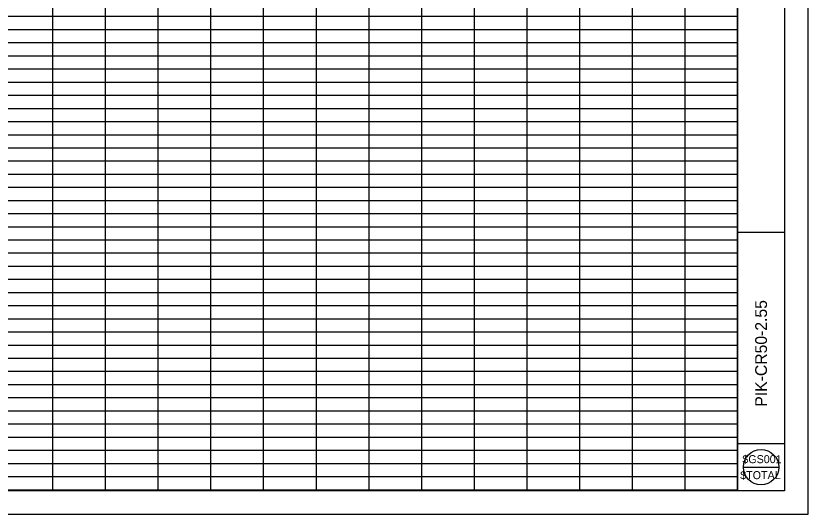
# Model space of a CAD drawing. Extents: x 0 to 34, y 0 to 22.
# Drawn here: x 17.17 to 34, y 0 to 10.6 of the extents above; entities that cross this region are included whole.
import ezdxf

# ---------------------------------------------------------------- set-up
doc = ezdxf.new("R2010")
doc.units = 0
for name, color, linetype in [('SH_Border', 7, 'Continuous'), ('SH_Cut_Line', 7, 'Continuous'), ('SH_Data', 7, 'Continuous')]:
    doc.layers.add(name, color=color, linetype=linetype)

msp = doc.modelspace()

# ---------------------------------------------------------------- linework, layer by layer
at = {"layer": 'SH_Border'}
for p, q in [((32.5, 0.5), (32.5, 21.5)), ((32.5, 6), (33.5, 6)), ((32.5, 1.5), (33.5, 1.5))]:
    msp.add_line(p, q, dxfattribs=at)
msp.add_lwpolyline([(2, 21.5), (33.5, 21.5), (33.5, 0.5), (2, 0.5)], close=True, dxfattribs=at)
at = {"layer": 'SH_Cut_Line'}
msp.add_lwpolyline([(0, 0), (34, 0), (34, 22), (0, 22)], close=True, dxfattribs=at)
at = {"layer": 'SH_Data'}
for p, q in [((17.945, 11.99), (17.945, 10.591)), ((19.065, 11.99), (19.065, 10.591)), ((20.184, 11.99), (20.184, 10.591)), ((21.304, 11.99), (21.304, 10.591)), ((22.423, 11.99), (22.423, 10.591)), ((23.543, 11.99), (23.543, 10.591)), ((24.663, 11.99), (24.663, 10.591)), ((25.782, 11.99), (25.782, 10.591)), ((26.902, 11.99), (26.902, 10.591)), ((28.022, 11.99), (28.022, 10.591)), ((29.141, 11.99), (29.141, 10.591)), ((30.261, 11.99), (30.261, 10.591)), ((31.38, 11.99), (31.38, 10.591)), ((32.5, 11.99), (32.5, 10.591)), ((15.706, 10.591), (17.945, 10.591)), ((17.945, 10.591), (21.304, 10.591)), ((17.945, 10.591), (17.945, 9.192)), ((19.065, 10.591), (19.065, 9.192)), ((20.184, 10.591), (20.184, 9.192)), ((21.304, 10.591), (22.423, 10.591)), ((21.304, 10.591), (21.304, 9.192)), ((22.423, 10.591), (28.022, 10.591)), ((22.423, 10.591), (22.423, 9.192)), ((23.543, 10.591), (23.543, 9.192)), ((24.663, 10.591), (24.663, 9.192)), ((25.782, 10.591), (25.782, 9.192)), ((26.902, 10.591), (26.902, 9.192)), ((28.022, 10.591), (32.5, 10.591)), ((28.022, 10.591), (28.022, 9.192)), ((29.141, 10.591), (29.141, 9.192)), ((30.261, 10.591), (30.261, 9.192)), ((31.38, 10.591), (31.38, 9.192)), ((32.5, 10.591), (32.5, 9.192)), ((15.706, 10.311), (17.945, 10.311)), ((17.945, 10.311), (21.304, 10.311)), ((21.304, 10.311), (22.423, 10.311)), ((22.423, 10.311), (28.022, 10.311)), ((28.022, 10.311), (32.5, 10.311)), ((15.706, 10.032), (17.945, 10.032)), ((17.945, 10.032), (21.304, 10.032)), ((21.304, 10.032), (22.423, 10.032)), ((22.423, 10.032), (28.022, 10.032)), ((28.022, 10.032), (32.5, 10.032)), ((15.706, 9.752), (17.945, 9.752)), ((17.945, 9.752), (21.304, 9.752)), ((21.304, 9.752), (22.423, 9.752)), ((22.423, 9.752), (28.022, 9.752)), ((28.022, 9.752), (32.5, 9.752)), ((15.706, 9.472), (17.945, 9.472)), ((17.945, 9.472), (21.304, 9.472)), ((21.304, 9.472), (22.423, 9.472)), ((22.423, 9.472), (28.022, 9.472)), ((28.022, 9.472), (32.5, 9.472)), ((15.706, 9.192), (17.945, 9.192)), ((17.945, 9.192), (21.304, 9.192)), ((17.945, 9.192), (17.945, 7.794)), ((19.065, 9.192), (19.065, 7.794)), ((20.184, 9.192), (20.184, 7.794)), ((21.304, 9.192), (22.423, 9.192)), ((21.304, 9.192), (21.304, 7.794)), ((22.423, 9.192), (28.022, 9.192)), ((22.423, 9.192), (22.423, 7.794)), ((23.543, 9.192), (23.543, 7.794)), ((24.663, 9.192), (24.663, 7.794)), ((25.782, 9.192), (25.782, 7.794)), ((26.902, 9.192), (26.902, 7.794)), ((28.022, 9.192), (32.5, 9.192)), ((28.022, 9.192), (28.022, 7.794)), ((29.141, 9.192), (29.141, 7.794)), ((30.261, 9.192), (30.261, 7.794)), ((31.38, 9.192), (31.38, 7.794)), ((32.5, 9.192), (32.5, 7.794)), ((15.706, 8.913), (17.945, 8.913)), ((17.945, 8.913), (21.304, 8.913)), ((21.304, 8.913), (22.423, 8.913)), ((22.423, 8.913), (28.022, 8.913)), ((28.022, 8.913), (32.5, 8.913)), ((15.706, 8.633), (17.945, 8.633)), ((17.945, 8.633), (21.304, 8.633)), ((21.304, 8.633), (22.423, 8.633)), ((22.423, 8.633), (28.022, 8.633)), ((28.022, 8.633), (32.5, 8.633)), ((15.706, 8.353), (17.945, 8.353)), ((17.945, 8.353), (21.304, 8.353)), ((21.304, 8.353), (22.423, 8.353)), ((22.423, 8.353), (28.022, 8.353)), ((28.022, 8.353), (32.5, 8.353)), ((15.706, 8.073), (17.945, 8.073)), ((17.945, 8.073), (21.304, 8.073)), ((21.304, 8.073), (22.423, 8.073)), ((22.423, 8.073), (28.022, 8.073)), ((28.022, 8.073), (32.5, 8.073)), ((15.706, 7.794), (17.945, 7.794)), ((17.945, 7.794), (21.304, 7.794)), ((17.945, 7.794), (17.945, 6.395)), ((19.065, 7.794), (19.065, 6.395)), ((20.184, 7.794), (20.184, 6.395)), ((21.304, 7.794), (22.423, 7.794)), ((21.304, 7.794), (21.304, 6.395)), ((22.423, 7.794), (28.022, 7.794)), ((22.423, 7.794), (22.423, 6.395)), ((23.543, 7.794), (23.543, 6.395)), ((24.663, 7.794), (24.663, 6.395)), ((25.782, 7.794), (25.782, 6.395)), ((26.902, 7.794), (26.902, 6.395)), ((28.022, 7.794), (32.5, 7.794)), ((28.022, 7.794), (28.022, 6.395)), ((29.141, 7.794), (29.141, 6.395)), ((30.261, 7.794), (30.261, 6.395)), ((31.38, 7.794), (31.38, 6.395)), ((32.5, 7.794), (32.5, 6.395)), ((15.706, 7.514), (17.945, 7.514)), ((17.945, 7.514), (21.304, 7.514)), ((21.304, 7.514), (22.423, 7.514)), ((22.423, 7.514), (28.022, 7.514)), ((28.022, 7.514), (32.5, 7.514)), ((15.706, 7.234), (17.945, 7.234)), ((17.945, 7.234), (21.304, 7.234)), ((21.304, 7.234), (22.423, 7.234)), ((22.423, 7.234), (28.022, 7.234)), ((28.022, 7.234), (32.5, 7.234)), ((15.706, 6.955), (17.945, 6.955)), ((17.945, 6.955), (21.304, 6.955)), ((21.304, 6.955), (22.423, 6.955)), ((22.423, 6.955), (28.022, 6.955)), ((28.022, 6.955), (32.5, 6.955)), ((15.706, 6.675), (17.945, 6.675)), ((17.945, 6.675), (21.304, 6.675)), ((21.304, 6.675), (22.423, 6.675)), ((22.423, 6.675), (28.022, 6.675)), ((28.022, 6.675), (32.5, 6.675)), ((15.706, 6.395), (17.945, 6.395)), ((17.945, 6.395), (21.304, 6.395)), ((17.945, 6.395), (17.945, 4.997)), ((19.065, 6.395), (19.065, 4.997)), ((20.184, 6.395), (20.184, 4.997)), ((21.304, 6.395), (22.423, 6.395)), ((21.304, 6.395), (21.304, 4.997)), ((22.423, 6.395), (28.022, 6.395)), ((22.423, 6.395), (22.423, 4.997)), ((23.543, 6.395), (23.543, 4.997)), ((24.663, 6.395), (24.663, 4.997)), ((25.782, 6.395), (25.782, 4.997)), ((26.902, 6.395), (26.902, 4.997)), ((28.022, 6.395), (32.5, 6.395)), ((28.022, 6.395), (28.022, 4.997)), ((29.141, 6.395), (29.141, 4.997)), ((30.261, 6.395), (30.261, 4.997)), ((31.38, 6.395), (31.38, 4.997)), ((32.5, 6.395), (32.5, 4.997)), ((15.706, 6.115), (17.945, 6.115)), ((17.945, 6.115), (21.304, 6.115)), ((21.304, 6.115), (22.423, 6.115)), ((22.423, 6.115), (28.022, 6.115)), ((28.022, 6.115), (32.5, 6.115)), ((15.706, 5.836), (17.945, 5.836)), ((17.945, 5.836), (21.304, 5.836)), ((21.304, 5.836), (22.423, 5.836)), ((22.423, 5.836), (28.022, 5.836)), ((28.022, 5.836), (32.5, 5.836)), ((15.706, 5.556), (17.945, 5.556)), ((17.945, 5.556), (21.304, 5.556)), ((21.304, 5.556), (22.423, 5.556)), ((22.423, 5.556), (28.022, 5.556)), ((28.022, 5.556), (32.5, 5.556)), ((15.706, 5.276), (17.945, 5.276)), ((17.945, 5.276), (21.304, 5.276)), ((21.304, 5.276), (22.423, 5.276)), ((22.423, 5.276), (28.022, 5.276)), ((28.022, 5.276), (32.5, 5.276)), ((15.706, 4.997), (17.945, 4.997)), ((17.945, 4.997), (21.304, 4.997)), ((17.945, 4.997), (17.945, 3.598)), ((19.065, 4.997), (19.065, 3.598)), ((20.184, 4.997), (20.184, 3.598)), ((21.304, 4.997), (22.423, 4.997)), ((21.304, 4.997), (21.304, 3.598)), ((22.423, 4.997), (28.022, 4.997)), ((22.423, 4.997), (22.423, 3.598)), ((23.543, 4.997), (23.543, 3.598)), ((24.663, 4.997), (24.663, 3.598)), ((25.782, 4.997), (25.782, 3.598)), ((26.902, 4.997), (26.902, 3.598)), ((28.022, 4.997), (32.5, 4.997)), ((28.022, 4.997), (28.022, 3.598)), ((29.141, 4.997), (29.141, 3.598)), ((30.261, 4.997), (30.261, 3.598)), ((31.38, 4.997), (31.38, 3.598)), ((32.5, 4.997), (32.5, 3.598)), ((15.706, 4.717), (17.945, 4.717)), ((17.945, 4.717), (21.304, 4.717)), ((21.304, 4.717), (22.423, 4.717)), ((22.423, 4.717), (28.022, 4.717)), ((28.022, 4.717), (32.5, 4.717)), ((15.706, 4.437), (17.945, 4.437)), ((17.945, 4.437), (21.304, 4.437)), ((21.304, 4.437), (22.423, 4.437)), ((22.423, 4.437), (28.022, 4.437)), ((28.022, 4.437), (32.5, 4.437)), ((15.706, 4.157), (17.945, 4.157)), ((17.945, 4.157), (21.304, 4.157)), ((21.304, 4.157), (22.423, 4.157)), ((22.423, 4.157), (28.022, 4.157)), ((28.022, 4.157), (32.5, 4.157)), ((15.706, 3.878), (17.945, 3.878)), ((17.945, 3.878), (21.304, 3.878)), ((21.304, 3.878), (22.423, 3.878)), ((22.423, 3.878), (28.022, 3.878)), ((28.022, 3.878), (32.5, 3.878)), ((33, 3.792), (33, 3.792)), ((15.706, 3.598), (17.945, 3.598)), ((17.945, 3.598), (21.304, 3.598)), ((17.945, 3.598), (17.945, 2.199)), ((19.065, 3.598), (19.065, 2.199)), ((20.184, 3.598), (20.184, 2.199)), ((21.304, 3.598), (22.423, 3.598)), ((21.304, 3.598), (21.304, 2.199)), ((22.423, 3.598), (28.022, 3.598)), ((22.423, 3.598), (22.423, 2.199)), ((23.543, 3.598), (23.543, 2.199)), ((24.663, 3.598), (24.663, 2.199)), ((25.782, 3.598), (25.782, 2.199)), ((26.902, 3.598), (26.902, 2.199)), ((28.022, 3.598), (32.5, 3.598)), ((28.022, 3.598), (28.022, 2.199)), ((29.141, 3.598), (29.141, 2.199)), ((30.261, 3.598), (30.261, 2.199)), ((31.38, 3.598), (31.38, 2.199)), ((32.5, 3.598), (32.5, 2.199)), ((15.706, 3.318), (17.945, 3.318)), ((17.945, 3.318), (21.304, 3.318)), ((21.304, 3.318), (22.423, 3.318)), ((22.423, 3.318), (28.022, 3.318)), ((28.022, 3.318), (32.5, 3.318)), ((15.706, 3.039), (17.945, 3.039)), ((17.945, 3.039), (21.304, 3.039)), ((21.304, 3.039), (22.423, 3.039)), ((22.423, 3.039), (28.022, 3.039)), ((28.022, 3.039), (32.5, 3.039)), ((15.706, 2.759), (17.945, 2.759)), ((17.945, 2.759), (21.304, 2.759)), ((21.304, 2.759), (22.423, 2.759)), ((22.423, 2.759), (28.022, 2.759)), ((28.022, 2.759), (32.5, 2.759)), ((15.706, 2.479), (17.945, 2.479)), ((17.945, 2.479), (21.304, 2.479)), ((21.304, 2.479), (22.423, 2.479)), ((22.423, 2.479), (28.022, 2.479)), ((28.022, 2.479), (32.5, 2.479)), ((15.706, 2.199), (17.945, 2.199)), ((17.945, 2.199), (21.304, 2.199)), ((17.945, 2.199), (17.945, 0.801)), ((19.065, 2.199), (19.065, 0.801)), ((20.184, 2.199), (20.184, 0.801)), ((21.304, 2.199), (22.423, 2.199)), ((21.304, 2.199), (21.304, 0.801)), ((22.423, 2.199), (28.022, 2.199)), ((22.423, 2.199), (22.423, 0.801)), ((23.543, 2.199), (23.543, 0.801)), ((24.663, 2.199), (24.663, 0.801)), ((25.782, 2.199), (25.782, 0.801)), ((26.902, 2.199), (26.902, 0.801)), ((28.022, 2.199), (32.5, 2.199)), ((28.022, 2.199), (28.022, 0.801)), ((29.141, 2.199), (29.141, 0.801)), ((30.261, 2.199), (30.261, 0.801)), ((31.38, 2.199), (31.38, 0.801)), ((32.5, 2.199), (32.5, 0.801)), ((15.706, 1.92), (17.945, 1.92)), ((17.945, 1.92), (21.304, 1.92)), ((21.304, 1.92), (22.423, 1.92)), ((22.423, 1.92), (28.022, 1.92)), ((28.022, 1.92), (32.5, 1.92)), ((15.706, 1.64), (17.945, 1.64)), ((17.945, 1.64), (21.304, 1.64)), ((21.304, 1.64), (22.423, 1.64)), ((22.423, 1.64), (28.022, 1.64)), ((28.022, 1.64), (32.5, 1.64)), ((15.706, 1.36), (17.945, 1.36)), ((17.945, 1.36), (21.304, 1.36)), ((21.304, 1.36), (22.423, 1.36)), ((22.423, 1.36), (28.022, 1.36)), ((28.022, 1.36), (32.5, 1.36)), ((15.706, 1.08), (17.945, 1.08)), ((17.945, 1.08), (21.304, 1.08)), ((21.304, 1.08), (22.423, 1.08)), ((22.423, 1.08), (28.022, 1.08)), ((28.022, 1.08), (32.5, 1.08)), ((33, 1.085), (33, 1.085)), ((32.625, 1), (33.375, 1)), ((15.706, 0.801), (17.945, 0.801)), ((17.945, 0.801), (21.304, 0.801)), ((17.945, 0.801), (17.945, 0.521)), ((19.065, 0.801), (19.065, 0.521)), ((20.184, 0.801), (20.184, 0.521)), ((21.304, 0.801), (22.423, 0.801)), ((21.304, 0.801), (21.304, 0.521)), ((22.423, 0.801), (28.022, 0.801)), ((22.423, 0.801), (22.423, 0.521)), ((23.543, 0.801), (23.543, 0.521)), ((24.663, 0.801), (24.663, 0.521)), ((25.782, 0.801), (25.782, 0.521)), ((26.902, 0.801), (26.902, 0.521)), ((28.022, 0.801), (32.5, 0.801)), ((28.022, 0.801), (28.022, 0.521)), ((29.141, 0.801), (29.141, 0.521)), ((30.261, 0.801), (30.261, 0.521)), ((31.38, 0.801), (31.38, 0.521)), ((32.5, 0.801), (32.5, 0.521)), ((33, 0.745), (33, 0.745)), ((15.706, 0.521), (17.945, 0.521)), ((17.945, 0.521), (21.304, 0.521)), ((21.304, 0.521), (22.423, 0.521)), ((22.423, 0.521), (28.022, 0.521)), ((28.022, 0.521), (32.5, 0.521))]:
    msp.add_line(p, q, dxfattribs=at)
msp.add_circle((33, 1), 0.375, dxfattribs=at)

# ---------------------------------------------------------------- texts
msp.add_text('PIK-CR50-2.55', height=0.25, rotation=90, dxfattribs=at).set_placement((33.125, 2.287))
for s, p in [('$GS001', (32.602, 1.085)), ('$TOTAL', (32.556, 0.745))]:
    msp.add_text(s, height=0.17, dxfattribs=at).set_placement(p)

doc.saveas('drawing.dxf')
